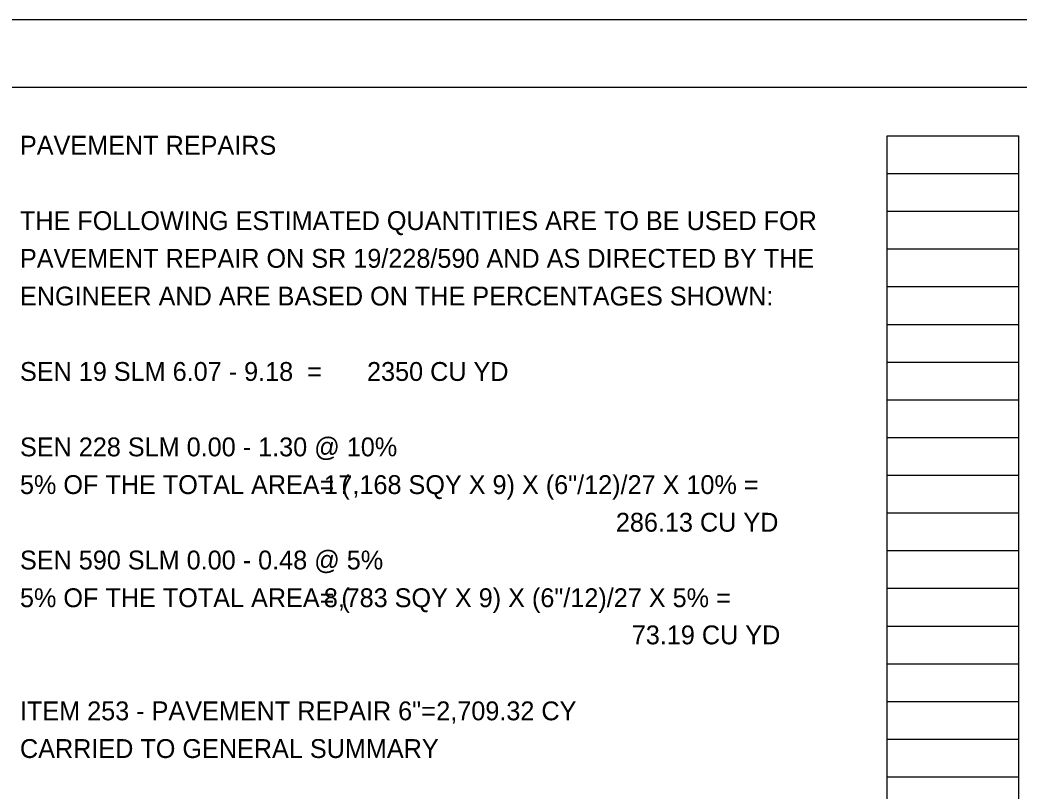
# Model space of a CAD drawing. Extents: x 0 to 34, y -1.4 to 22.
# Drawn here: x 17.24 to 24.66, y 16.27 to 22 of the extents above; entities that cross this region are included whole.
import ezdxf

# ---------------------------------------------------------------- set-up
doc = ezdxf.new("R2010")
doc.units = 0
for name, color, linetype in [('Default', 7, 'Continuous'), ('SH_Border', 7, 'Continuous'), ('SH_Cut_Line', 7, 'Continuous'), ('SH_Data', 7, 'Continuous'), ('SH_Text', 7, 'Continuous')]:
    doc.layers.add(name, color=color, linetype=linetype)

msp = doc.modelspace()

# ---------------------------------------------------------------- linework, layer by layer
at = {"layer": 'SH_Border'}
msp.add_lwpolyline([(1.5, 21.5), (33.5, 21.5), (33.5, 0.5), (1.5, 0.5)], close=True, dxfattribs=at)
at = {"layer": 'SH_Cut_Line'}
msp.add_lwpolyline([(0, 0), (34, 0), (34, 22), (0, 22)], close=True, dxfattribs=at)
at = {"layer": 'SH_Data'}
for p, q in [((23.68, 0.98), (23.68, 21.14)), ((23.68, 21.14), (24.66, 21.14)), ((24.66, 0.98), (24.66, 21.14)), ((23.68, 20.86), (24.66, 20.86)), ((23.68, 20.58), (24.66, 20.58)), ((23.68, 20.3), (24.66, 20.3)), ((23.68, 20.02), (24.66, 20.02)), ((23.68, 19.74), (24.66, 19.74)), ((23.68, 19.46), (24.66, 19.46)), ((23.68, 19.18), (24.66, 19.18)), ((23.68, 18.9), (24.66, 18.9)), ((23.68, 18.62), (24.66, 18.62)), ((23.68, 18.34), (24.66, 18.34)), ((23.68, 18.06), (24.66, 18.06)), ((23.68, 17.78), (24.66, 17.78)), ((23.68, 17.5), (24.66, 17.5)), ((23.68, 17.22), (24.66, 17.22)), ((23.68, 16.94), (24.66, 16.94)), ((23.68, 16.66), (24.66, 16.66)), ((23.68, 16.38), (24.66, 16.38))]:
    msp.add_line(p, q, dxfattribs=at)

# ---------------------------------------------------------------- texts
at = {"layer": 'Default'}
for s, p in [('2350 CU YD', (19.8179, 19.32)), ('286.13 CU YD', (21.6662, 18.2005)), ('73.19 CU YD', (21.7843, 17.3642)), ('ITEM 253 - PAVEMENT REPAIR 6"= ', (17.24, 16.8)), ('2,709.32 CY ', (20.3322, 16.8)), ('CARRIED TO GENERAL SUMMARY', (17.24, 16.52))]:
    msp.add_text(s, height=0.14, dxfattribs=at).set_placement(p)
at = {"layer": 'SH_Text'}
for s, p in [('PAVEMENT REPAIRS', (17.24, 21)), ('THE FOLLOWING ESTIMATED QUANTITIES ARE TO BE USED FOR', (17.24, 20.44)), ('PAVEMENT REPAIR ON SR 19/228/590 AND AS DIRECTED BY THE ', (17.24, 20.16)), ('ENGINEER AND ARE BASED ON THE PERCENTAGES SHOWN:', (17.24, 19.88)), ('SEN 19 SLM 6.07 - 9.18  = ', (17.24, 19.32)), ('SEN 228 SLM 0.00 - 1.30 @ 10% ', (17.24, 18.76)), ('5% OF THE TOTAL AREA= (', (17.24, 18.48)), ('7,168 SQY X 9) X (6"/12)/27 X 10% =', (19.6053, 18.48)), ('1', (19.4969, 18.48)), ('SEN 590 SLM 0.00 - 0.48 @ 5% ', (17.24, 17.92)), ('5% OF THE TOTAL AREA= (', (17.24, 17.64)), ('8,', (19.4969, 17.64)), ('783 SQY X 9) X (6"/12)/27 X 5% =', (19.6588, 17.64))]:
    msp.add_text(s, height=0.14, dxfattribs=at).set_placement(p)

doc.saveas('drawing.dxf')
